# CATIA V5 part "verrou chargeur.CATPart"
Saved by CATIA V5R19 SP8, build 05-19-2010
Part number: verrou chargeur
Bounding box of the stored display mesh (mm): x 0 to 8, y 0 to 29, z -10 to 5
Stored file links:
  C:\Users\Arthur\Desktop\Catia parts\GLOCK\Poignée\verrou chargeur.CATPart
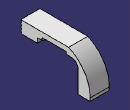
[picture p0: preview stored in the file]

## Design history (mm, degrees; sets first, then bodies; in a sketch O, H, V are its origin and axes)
Set1
  Sketch1 on yz-plane, origin (0, 0, 0), H (0, 1, 0), V (0, 0, 1)
    construction line L1 (0, 0) -> (0, 5)
    point P1 (0, 5)
    line L2 (0, 5) -> (20, 5)
    point P2 (29, 5)
    line L3 (0, 0) -> (6.954, 0)
    line L4 (29, -8.7477) -> (29, -10)
    arc A1 centre (14, -8.7477) radius 15 from (20, 5) to (29, -8.7477) cw
    point P5 (20, 5)
    line L5 (29, -10) -> (24, -10)
    line L6 (24, -10) -> (24, -1)
    line L7 (21, 2) -> (6.954, 2)
    point P9 (6.954, 2)
    arc A2 centre (21, -1) radius 3 from (21, 2) to (24, -1) cw
    line L8 (6.954, 0) -> (6.954, 2)
    point P13 (6.954, 2)
    axis line L9 (0.5, 9.9304) -> (0.5, -2.3699)
    line L10 (0, 5) -> (0.5, 4.375)
    point P16 (0.5, 4.375)
    line L11 (0.5, 4.375) -> (0, 3.75)
    point P17 (0.5, 4.375)
    point P18 (0, 3.75)
    line L12 (0, 3.75) -> (0.5, 3.125)
    point P19 (0.5, 3.125)
    line L13 (0.5, 3.125) -> (0, 2.5)
    point P20 (0, 2.5)
    point P21 (0.5, 3.125)
    line L14 (0, 2.5) -> (0.5, 1.875)
    point P22 (0.5, 1.875)
    line L15 (0.5, 1.875) -> (0, 1.25)
    point P23 (0, 1.25)
    line L16 (0, 1.25) -> (0.5, 0.625)
    point P24 (0, 1.25)
    point P25 (0.5, 0.625)
    line L17 (0.5, 0.625) -> (0, 0)
    point P26 (0, 0)
    distance P1 P2 = 29
    radius A1 = 15
    length L1 = 5
    distance L2 L5 = 15
    distance P5 L1 = 20
    length L5 = 5
    radius A2 = 3
    distance L7 L2 = 3
    distance L1 L9 = 0.5
    distance P23 O = 1.25
    distance P18 P1 = 1.25
    distance P20 P18 = 1.25
    distance P25 L3 = 0.625
    distance P25 P22 = 1.25
    distance P22 P19 = 1.25
    distance P19 P16 = 1.25
    vertical: L1 V, L4 V, L6 V, L8 V, L9 V
    horizontal: L2 H, L3 H, L5 H, L7 H
    coincidence: L2 P2, L4 P2, P13 L7, P9 P13, P16 L9, P17 L10, P17 L9, P18 L1, P19 L9, P20 L1, P21 P19, P22 L9, P23 L1, P24 L15, P25 L9, P26 H, L17 O, P24 P23
    tangency: A1 L4, A2 L7, A2 L6
Body1 (main body)
  Pad1: profile Sketch1, direction (1, 0, 0), length 8
  Sketch2 on face of Pad1 from Sketch1.L7, origin (0, 0, 2), H (1, 0, 0), V (0, -1, 0)
    line L1 (8, -8.977) -> (8, -18.977)
    point P1 (8, -8.977)
    point P2 (8, -18.977)
    line L2 (8, -8.977) -> (0, -13.477)
    point P3 (0, -13.477)
    line L3 (0, -13.477) -> (0, -14.477)
    point P4 (0, -14.477)
    line L4 (0, -14.477) -> (8, -18.977)
    axis line L5 (20.3867, -13.977) -> (1.0202, -13.977)
    reference projected line E1 (8, -6.954) -> (8, -21) from edge [face of Pad1 from Sketch1.L7 | end face of Pad1]
    reference projected line E2 (0, -21) -> (8, -21) from edge [face of Pad1 from Sketch1.A2 | face of Pad1 from Sketch1.L7]
    reference projected line E3 (0, -6.954) -> (8, -6.954) from edge [face of Pad1 from Sketch1.L7 | face of Pad1 from Sketch1.L8]
    reference projected line E4 (0, -6.954) -> (0, -21) from edge [start face of Pad1 | face of Pad1 from Sketch1.L7]
    length L3 = 1
    length L1 = 10
    vertical: L1 V, L3 V
    horizontal: L5 H
    symmetry: P2 P1 L5, P4 P3 L5, E2 E3 L5
    coincidence: L1 E1, L3 E4
  Pocket1: profile Sketch2, direction (0, 0, 1), length 1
